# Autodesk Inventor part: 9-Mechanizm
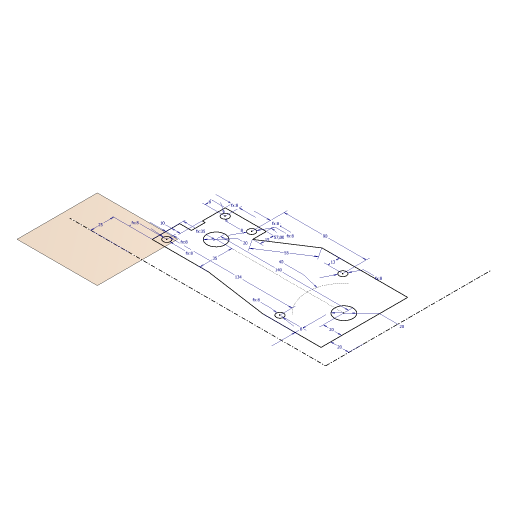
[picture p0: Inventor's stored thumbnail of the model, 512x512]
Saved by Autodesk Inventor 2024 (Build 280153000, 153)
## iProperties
Company: ATC
Shininess: 20.0
Angle Display Precision: 2
Document Length Units: 11269
Document Angle Units: 11279
Document Time Units: 11290
Document Mass Units: 11283
Document Length Units Precision: 3
Document Angle Units Precision: 2
Created: 2023-03
Part Number: 9-Mechanizm
Material: Kurs-AJ
Document SubType Name: Modelowanie
Designer: Andrzej Jaskulski
Density: 1 g/cm^3
Appearance: Kurs-AJ
Checked By: A.J.
Engr Approved By: Andrzej Jaskulski
Mfg Approved By: Andrzej Jaskulski
Authority: A.J.
Density: 0.0
Volumn: 0.0
Area: 0.0
PropertySet Name: Model Information
Control State: 0
Master: False
Checked Out: False
Title: A.J.: Kurs R2024-MEP
Author: Andrzej Jaskulski
Revision Number: 1/24
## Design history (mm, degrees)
node "Płaszczyzna konstrukcyjna5"
node "Początek"
  node "Płaszczyzna YZ"
  node "Płaszczyzna XZ"
  node "Płaszczyzna XY"
  node "Oś X"
  node "Oś Y"
  node "Oś Z"
sketch "Szkic1"
  geometry: L1 (60, 60)-(60, 90); L2 (60, 90)-(73, 90) reference; L3 (73, 90)-(73, 105) reference; L4 (73, 105)-(70, 105) reference; L5 (70, 105)-(70, 130) reference; L6 (70, 130)-(115, 130) reference; L7 (115, 130)-(115, 115) reference; L8 (115, 115)-(161.127, 144.955); L9 (161.127, 144.955)-(255, 144.955); L10 (60, 60)-(121.629, 60) reference; L11 (121.629, 60)-(191.251, 50) reference; L12 (191.251, 50)-(255, 50) reference; L13 (255, 50)-(255, 144.955); L14 (-4.978, 35)-(275, 35); L15 (275, 35)-(275, 216.134); L16 (95, 95)-(235, 95); C1 r 10 at (95, 95); C2 r 4 at (68, 68); C3 r 4 at (78, 122); C4 r 4 at (197, 131.955); C5 r 4 at (202, 58); C6 r 4 at (107, 122); C7 r 10 at (235, 95); A1 r 40 centre (235, 95) between (209.984, 126.212) and (208.349, 65.171)
  constraints: 32 end point, 8 centre point, 6 horizontal, 4 perpendicular, 4 vertical, 2 point on circle, 1 coincident, 1 horizontal alignment, 1 vertical alignment, 1 other
  dimensions: "d0" = 20 diameter of C1; "d5" = 10 distance between parallel lines of L5 L1; "d6" = 8 diameter of C3; "d7" = 8 diameter of C6 (= d6); "d8" = 8 diameter of C2 (= d6); "d9" = 8 diameter of C4 (= d6); "d10" = 8 diameter of C5 (= d6); "d11" = 8 distance from line of L6 C3.centre; "d12" = 8 distance from line of C3.centre L5 (= d11); "d13" = 8 distance from line of C6.centre L7 (= d11); "d14" = 8 distance from line of C2.centre L10 (= d11); "d15" = 8 distance from line of C2.centre L1 (= d11); "d20" = 35 distance from line of L10 L16.start; "d21" = 35 distance from line of L1 L16.start (= d20); "d54" = 134 horizontal distance of C5.centre C2.centre; "d55" = 90 horizontal distance of C4.centre C6.centre; "d58" = 20 distance between parallel lines of L13 L15; "d59" = 25 distance between parallel lines of L10 L14; "d61" = 20 diameter of C7; "d62" = 20 distance from line of L13 L16.end; "d63" = 40 radius of A1; "d64" = 140 distance of L16.end L16.start; "d65" = 13 distance from line of L9 C4.centre; "d66" = 8 distance from line of L12 C5.centre; "d67" = 15 distance of L6.end L7.end; "d68" = 55 distance of L7.end L8.end; "d69" = 57 deg angle of L8 L7
node "Korpusy bryłowe"
node "Korpusy powierzchniowe"
node "Punkt środkowy"
